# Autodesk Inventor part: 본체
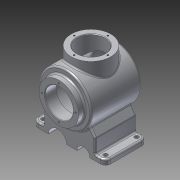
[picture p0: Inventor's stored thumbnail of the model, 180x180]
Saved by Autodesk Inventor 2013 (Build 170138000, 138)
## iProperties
Created: 2018-08
Part Number: 본체
Material: 알루미늄 6061
Document SubType Name: Modeling
Designer: Administrator
Density: 2.71 g/cm^3
Mass: 1880.41 g
Surface Area: 1087.48 cm^2
Volume: 693.88 cm^3
Author: Administrator
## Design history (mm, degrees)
sketch "스케치1"
  geometry: L1 (0, 0)-(120, 0); L2 (0, 27)-(0, 38); L3 (0, 38)-(12, 38); L4 (12, 38)-(12, 47); L5 (15, 50)-(106.762, 50); L6 (25, 40)-(100.125, 40); L7 (0, 27)-(22, 27); L8 (22, 27)-(22, 37); A1 r 116 centre (4, 0) between (120, 0) and (109.49, 48.248); A2 r 106 centre (4, 0) between (110, 0) and (102.925, 38.078); A3 r 3 centre (25, 37) between (25, 40) and (22, 37); A4 r 3 centre (100.125, 37) between (102.925, 38.078) and (100.125, 40); A5 r 3 centre (15, 47) between (15, 50) and (12, 47); A6 r 3 centre (106.762, 47) between (109.49, 48.248) and (106.762, 50); 2 further points
  constraints: 16 end point, 14 point on circle, 8 tangent, 6 centre point, 4 point on line, 3 equal radius, 3 parallel, 3 perpendicular, 1 horizontal
  dimensions: "d0" = 120 distance of L1.start L1.end; "d2" = 116 radius of A1; "d3" = 10 radial gap between concentric circles of A1 A2; "d4" = 54 diameter of L7 L1; "d5" = 100 diameter of L5 L1; "d6" = 76 diameter of L3 L1; "d7" = 22 distance of L2.start L7.end; "d8" = 12 distance of L2.end L3.end; "d9" = 108 distance from line of L1.end L4; "d10" = 80 diameter of L6 L1; "d11" = 3 radius of A3
revolve "회전1" sketch "스케치1" stored, may be unused: angle "d12" = 90 deg
sketch "스케치2" dims "d13" = 65
  geometry: C1 r 38 at (0, 0) reference; C2 r 27 at (0, 0) reference; C3 r 2 at (32.5, 0); C4 r 2 at (0, 32.5); C5 r 2 at (-32.5, 0); C6 r 2 at (0, -32.5); 1 further point
  constraints: 4 centre point, 2 horizontal alignment, 1 coincident, 11 other
  dimensions: "d15" = 4 diameter of C3; "d18" = 360 deg dimension on C1.centre C3.centre (derived)
hole "구멍1" sketch "스케치2" at (32.5, 0), (0, -32.5), (-32.5, 0), (0, 32.5) diameter "d20" = 3.242; stored, may be unused: countersink angle "d24" = 90 deg, drill point angle "d26" = 118 deg; dims "d21" = 8, "d22" = 4, "d23" = 2, "d25" = 10
fillet "모깎기1" dims "d27" = 3
chamfer "모따기1" distance "d28" = 1; stored, may be unused: second distance "d29" = 2, angle "d30" = 45 deg
node "작업 평면1"
sketch "스케치3"
  geometry: L1 (30, 70)-(90, 70); L2 (100, 60)-(100, -60); L3 (90, -70)-(30, -70); L4 (20, -60)-(20, 60); L5 (12, -47)-(12, 47) reference; C1 r 4 at (30, 60); C2 r 4 at (90, 60); C3 r 4 at (90, -60); C4 r 4 at (30, -60); A1 r 10 centre (30, 60) between (30, 70) and (20, 60); A2 r 10 centre (90, 60) between (100, 60) and (90, 70); A3 r 10 centre (90, -60) between (90, -70) and (100, -60); A4 r 10 centre (30, -60) between (20, -60) and (30, -70); 4 further points
  constraints: 8 centre point, 8 end point, 8 point on circle, 8 tangent, 6 equal radius, 6 point on line, 4 coincident, 2 parallel, 1 horizontal, 1 perpendicular
  dimensions: "d32" = 140 distance of point (100, 70) point (100, -70); "d34" = 70 distance from line of point (0, 0) L1; "d35" = 80 distance of point (20, 70) point (100, 70); "d36" = 8 distance between parallel lines of L5 L4; "d37" = 10 radius of A1; "d38" = 8 diameter of C1
extrude "돌출1" join sketch "스케치3" distance "d39" = 10; taper "d40" = 0 deg
node "작업 평면2"
sketch "스케치4"
  geometry: L1 (10, 0)-(10, 120) reference; L2 (10, 124)-(10, 116) reference; L3 (10, 120)-(10, 130) reference; L4 (0, 130)-(10, 130) reference; L5 (10, 4)-(10, -4) reference; L6 (10, -10)-(10, 0) reference; L7 (0, -10)-(10, -10) reference; L8 (60.493, 93.726)-(37.251, 110); L9 (37.251, 110)-(10, 110); L10 (60.493, 26.274)-(37.251, 10); L11 (37.251, 10)-(10, 10); C1 r 50 at (82, 60) reference; C2 r 38.078 at (82, 60) reference; A1 r 40 centre (82, 60) between (60.493, 93.726) and (60.493, 26.274) reference; 1 further point
  constraints: 8 end point, 2 perpendicular, 2 point on circle, 2 point on line, 2 vertical alignment
  dimensions: "d41" = 20 vertical distance of L7.start L11.end; "d42" = 20 vertical distance of L4.start L9.end; "d43" = 35 deg angle of L9 L8; "d44" = 35 deg angle of L10 L11
extrude "돌출2" join sketch "스케치4" stored distance "d45" = 80; taper "d46" = 0 deg
sketch "스케치5"
  geometry: L1 (0, 120)-(0, 0) reference; A1 r 50 centre (82, 60) between (51.775, 99.83) and (51.775, 20.17) reference; A2 r 17.5 centre (0, 82.5) between (0, 65) and (0, 100); A3 r 12.5 centre (0, 32.5) between (0, 20) and (0, 45)
  constraints: 6 point on line, 4 point on circle, 2 centre point
  dimensions: "d50" = 22.5 vertical distance of A2.centre A1.centre; "d51" = 27.5 vertical distance of A1.centre A3.centre; "d52" = 17.5 radius of A2; "d53" = 12.5 radius of A3
extrude "돌출3" cut sketch "스케치5" stored distance "d54" = 80; taper "d55" = 0 deg
fillet "모깎기2" dims "d56" = 3
fillet "모깎기3" dims "d57" = 3
fillet "모깎기4" dims "d58" = 3
fillet "모깎기5" dims "d59" = 3
node "작업 평면3"
sketch "스케치6"
  geometry: L1 (12, -47)-(12, 47) reference; C1 r 38 at (62, 0); 1 further point
  constraints: 1 centre point, 1 horizontal alignment
  dimensions: "d61" = 50 distance from line of L1 C1.centre; "d62" = 76 diameter of C1
extrude "돌출4" join sketch "스케치6" stored distance "d63" = 80; taper "d64" = 0 deg
sketch "스케치7" dims "d65" = 65
  geometry: C1 r 38 at (0, 0) reference; C2 r 2 at (0, 32.5); C3 r 2 at (-32.5, 0); C4 r 2 at (0, -32.5); C5 r 2 at (32.5, 0); 2 further points
  constraints: 4 centre point, 2 vertical alignment, 1 coincident, 11 other
  dimensions: "d67" = 4 diameter of C2; "d70" = 360 deg dimension on C1.centre C2.centre (derived)
hole "구멍2" sketch "스케치7" at (0, 32.5), (32.5, 0), (0, -32.5), (-32.5, 0) diameter "d72" = 3.242; stored, may be unused: countersink angle "d76" = 90 deg, drill point angle "d78" = 118 deg; dims "d73" = 8, "d74" = 4, "d75" = 2, "d77" = 10
sketch "스케치8"
  geometry: C1 r 38 at (0, 0) reference; C2 r 27 at (0, 0); 1 further point
  constraints: 1 centre point, 1 coincident
  dimensions: "d79" = 54 diameter of C2
extrude "돌출5" cut sketch "스케치8" stored distance "d81" = 80; taper "d82" = 0 deg
chamfer "모따기2" distance "d83" = 1; stored, may be unused: second distance "d84" = 2, angle "d85" = 45 deg
fillet "모깎기6" dims "d86" = 3
node "작업 평면4"
sketch "스케치9"
  geometry: C1 r 32.5 at (0, 0); 1 further point
  constraints: 1 centre point, 1 coincident, 1 other
  dimensions: "d87" = 65 diameter of C1
feature "엠보싱1" sketch "스케치9" dims "d0" = 120, "d2" = 116, "d3" = 10, "d4" = 54, "d5" = 100, "d6" = 76, "d7" = 22, "d8" = 12, "d9" = 108, "d10" = 80, "d11" = 3, "d89" = 0.5, "d90" = 0
node "솔리드1"
node "투영된 루프1"
other parameters: "d31" = -82, "d60" = 65
